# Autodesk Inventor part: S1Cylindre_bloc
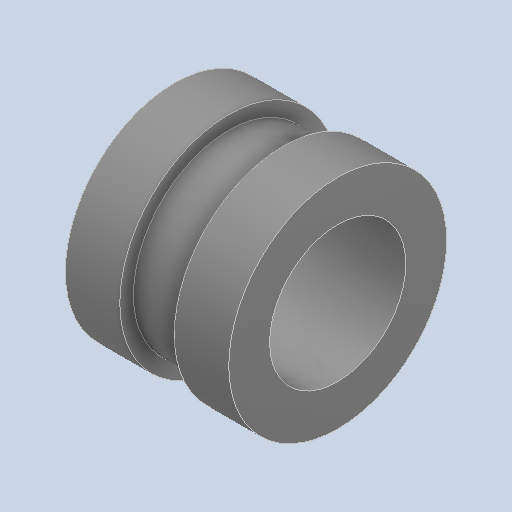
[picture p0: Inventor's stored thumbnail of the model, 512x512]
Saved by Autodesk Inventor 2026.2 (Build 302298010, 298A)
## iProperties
Created: 1601-01
Part Number: S1Cylindre_bloc
Material: Silicon Rubber
Document SubType Name: Modeling
Designer: mel
Density: 1.2465 g/cm^3
Appearance: glossy rubber
Author: mel
Sending System: SOLIDWORKS 2023
Part Number: Cylindre_bloc
Last Saved Date: 2025-04-02
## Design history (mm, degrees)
feature "Révolution1"
node "Solide1"
